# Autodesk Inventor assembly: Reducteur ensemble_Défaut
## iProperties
Shininess: 64.0
Length Units: 11269
Angle Units: 11279
Time Units: 11290
Mass Units: 11283
Length Display Precision: 3
Angle Display Precision: 2
Compacted: True
Created: 2006-01
Part Number: Reducteur ensemble_Défaut
Document SubType Name: Assembly
Designer: Fricot
Density: 0.0
Volumn: 0.0
Area: 0.0
PropertySet Name: Model Information
Control State: 0
Master: False
Checked Out: False
Author: Fricot
